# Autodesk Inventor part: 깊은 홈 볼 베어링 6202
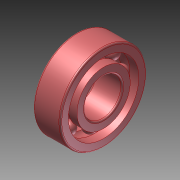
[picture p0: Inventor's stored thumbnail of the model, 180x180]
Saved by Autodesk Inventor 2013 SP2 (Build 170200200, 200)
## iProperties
Created: 2024-11
Part Number: 깊은 홈 볼 베어링 6202
Material: Generic
Document SubType Name: Modeling
Designer: a
Density: 1 g/cm^3
Author: a
변환 표준: STEP AP214IS
전처리기: Build: 200, Release: 2013 SP2 Update 6 - Date: Thu 07/17/2014
전송 단위: 밀리미터
불확실성: 0.01
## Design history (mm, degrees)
node "깊음 홈 볼 베어링 62021"
body "Solid1"
node "Solid1_1"
node "Solid1_2"
node "Solid1_3"
node "Solid1_4"
node "Solid1_5"
node "Solid1_6"
node "Solid1_7"
node "Solid1_8"
node "Solid1_9"
node "기준1"
node "기준2"
node "기준3"
node "기준4"
node "기준5"
node "기준6"
node "기준7"
node "기준8"
node "기준9"
node "기준10"
